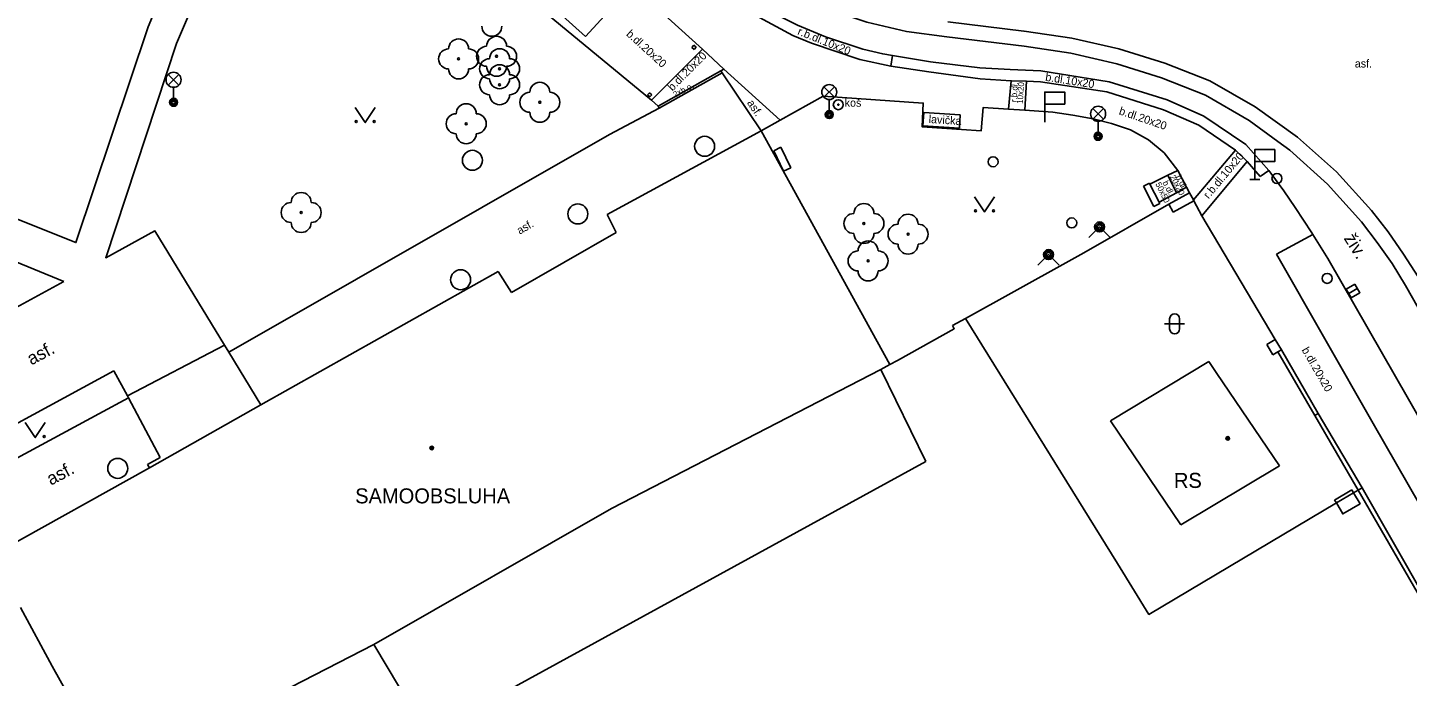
# Model space of a CAD drawing. Extents: x -600391 to -599491, y -1160176 to -1159402.
# Drawn here: x -600032.7 to -599963.7, y -1159815.5 to -1159783.1 of the extents above; entities that cross this region are included whole.
import ezdxf

# ---------------------------------------------------------------- set-up
doc = ezdxf.new("R2010")
doc.units = 0
for name, color, linetype in [('Level 10', 7, 'Continuous'), ('Level 11', 7, 'Continuous'), ('Level 13', 7, 'Continuous'), ('Level 22', 7, 'Continuous'), ('Level 24', 7, 'Continuous'), ('Level 25', 7, 'Continuous'), ('Level 27', 7, 'Continuous'), ('Level 28', 7, 'Continuous'), ('Level 31', 7, 'Continuous'), ('Level 33', 7, 'Continuous'), ('Level 34', 7, 'Continuous'), ('Level 36', 7, 'Continuous'), ('Level 39', 7, 'Continuous'), ('Level 40', 7, 'Continuous'), ('Level 41', 7, 'Continuous'), ('Level 42', 7, 'Continuous'), ('Level 5', 7, 'Continuous'), ('Level 53', 7, 'Continuous'), ('Level 6', 7, 'Continuous'), ('Level 7', 7, 'Continuous'), ('Level 8', 7, 'Continuous')]:
    doc.layers.add(name, color=color, linetype=linetype)

msp = doc.modelspace()

# ---------------------------------------------------------------- linework, layer by layer
at = {"layer": 'Level 10'}
for points in [[(-599996.32, -1159781.8), (-599995.99, -1159782), (-599995.5, -1159782.3), (-599994.17, -1159782.98), (-599992.77, -1159783.55), (-599990.91, -1159784.17)], [(-599985.05, -1159785.11), (-599987.52, -1159784.81), (-599989.42, -1159784.49), (-599989.91, -1159784.41), (-599990.91, -1159784.17)], [(-599985.05, -1159785.11), (-599983.54, -1159785.19)], [(-599983.54, -1159785.19), (-599982.01, -1159785.26), (-599978.59, -1159785.81), (-599975.69, -1159786.71), (-599973.85, -1159787.52), (-599971.76, -1159788.94), (-599970.6, -1159790.24)], [(-599970.6, -1159790.24), (-599970.51, -1159790.37), (-599969.86, -1159791.25)], [(-599969.86, -1159791.25), (-599969.29, -1159792.09), (-599968.46, -1159793.36), (-599968.41, -1159793.44), (-599967.66, -1159794.63)], [(-599969.86, -1159791.25), (-599969.29, -1159792.09), (-599968.46, -1159793.36), (-599968.41, -1159793.44), (-599967.66, -1159794.63)], [(-599967.66, -1159794.63), (-599963.63, -1159801.67), (-599957.71, -1159812.03)]]:
    msp.add_lwpolyline(points, dxfattribs=at)
at = {"layer": 'Level 11'}
for points in [[(-599983.62, -1159787.18), (-599983.48, -1159785.75), (-599985.04, -1159785.65), (-599987.61, -1159785.3), (-599989.51, -1159785.02), (-599991.06, -1159784.69), (-599993.47, -1159783.87), (-599994.4, -1159783.49), (-599996.28, -1159782.47), (-599998.5, -1159780.99), (-600001, -1159778.93), (-600003.59, -1159775.97), (-600005.32, -1159773.3), (-600006.97, -1159769.34), (-600007.51, -1159766.96), (-600007.91, -1159763.43), (-600007.81, -1159760.39)], [(-600001.14, -1159787.02), (-599998, -1159785.25), (-599997.85, -1159785.17), (-599998.92, -1159784.17), (-600002.35, -1159781.06), (-600004.81, -1159778.83), (-600008.12, -1159775.8), (-600008.17, -1159775.75)], [(-600043.13, -1159779.41), (-600038.01, -1159778.77), (-600031.48, -1159778.39), (-600027.46, -1159778.27), (-600025.46, -1159778.33), (-600025.01, -1159779.18), (-600026.63, -1159783.05), (-600030.24, -1159793.84), (-600038.89, -1159790.39)], [(-600022.81, -1159798.97), (-600026.29, -1159793.26), (-600028.75, -1159794.6), (-600025.22, -1159783.89), (-600023.54, -1159779.99), (-600022.13, -1159778.48), (-600016.23, -1159778.91)], [(-600007.53, -1159781.7), (-600001.46, -1159786.72), (-600001.14, -1159787.02), (-600001.09, -1159787.12)], [(-599994.52, -1159781.35), (-599992.65, -1159782.18), (-599990.71, -1159782.82), (-599988.72, -1159783.29), (-599986.7, -1159783.56)], [(-599986.7, -1159783.56), (-599982.83, -1159784.03)], [(-600001.46, -1159786.72), (-599998.92, -1159784.17)], [(-599999.45, -1159784.09), (-599999.35, -1159783.98)], [(-599999.34, -1159784.19), (-599999.45, -1159784.09)], [(-599999.35, -1159783.98), (-599999.24, -1159784.08)], [(-599999.24, -1159784.08), (-599999.34, -1159784.19)], [(-599989.51, -1159785.02), (-599989.42, -1159784.49)], [(-599982.83, -1159784.03), (-599980.5, -1159784.38), (-599978.21, -1159784.91), (-599975.97, -1159785.6), (-599973.78, -1159786.47)], [(-599997.85, -1159785.17), (-599995.04, -1159787.72)], [(-599997.94, -1159785.35), (-600001.09, -1159787.12)], [(-599997.94, -1159785.35), (-599998, -1159785.25)], [(-599997.94, -1159785.35), (-599995.99, -1159788.26)], [(-599983.48, -1159785.75), (-599982.72, -1159785.78)], [(-599982.81, -1159787.22), (-599982.72, -1159785.78), (-599982.03, -1159785.8)], [(-599982.03, -1159785.8), (-599978.7, -1159786.31)], [(-600001.66, -1159786.46), (-600001.56, -1159786.35)], [(-600001.55, -1159786.56), (-600001.66, -1159786.46)], [(-600001.56, -1159786.35), (-600001.45, -1159786.45)], [(-600001.45, -1159786.45), (-600001.55, -1159786.56)], [(-599995.99, -1159788.26), (-599995.04, -1159787.72), (-599992.88, -1159786.53), (-599987.88, -1159786.87), (-599987.94, -1159788.05), (-599984.98, -1159788.25), (-599984.89, -1159787.09), (-599983.62, -1159787.18), (-599982.81, -1159787.22), (-599981.41, -1159787.33), (-599980.41, -1159787.47), (-599979.39, -1159787.65), (-599978.47, -1159787.89), (-599977.53, -1159788.21), (-599976.63, -1159788.71), (-599975.84, -1159789.36), (-599975.16, -1159790.24)], [(-599978.7, -1159786.31), (-599975.87, -1159787.2)], [(-599973.78, -1159786.47), (-599971.59, -1159787.74), (-599970.15, -1159788.79)], [(-600001.09, -1159787.12), (-600003.57, -1159788.44)], [(-599975.87, -1159787.2), (-599974.11, -1159787.98), (-599972.27, -1159789.23)], [(-600003.57, -1159788.44), (-600022.59, -1159799.32)], [(-599972.27, -1159789.23), (-599974.38, -1159791.71)], [(-599972.27, -1159789.23), (-599971.69, -1159789.79)], [(-599970.15, -1159788.79), (-599969.55, -1159789.23), (-599967.67, -1159790.93), (-599965.98, -1159792.81)], [(-599970.15, -1159788.79), (-599969.55, -1159789.23), (-599967.67, -1159790.93), (-599965.98, -1159792.81)], [(-599973.96, -1159792.5), (-599971.69, -1159789.79)], [(-599971.69, -1159789.79), (-599971.04, -1159790.54)], [(-600044.16, -1159790.33), (-600030.85, -1159795.78)], [(-599976.55, -1159790.93), (-599975.65, -1159790.48), (-599975.16, -1159790.24)], [(-599975.65, -1159790.48), (-599975.23, -1159791.35)], [(-599975.16, -1159790.24), (-599974.72, -1159791.07)], [(-599971.04, -1159790.54), (-599970.6, -1159790.24)], [(-599976.09, -1159791.82), (-599975.23, -1159791.35)], [(-599975.23, -1159791.35), (-599974.72, -1159791.07)], [(-599974.72, -1159791.07), (-599974.57, -1159791.36)], [(-599968.41, -1159793.44), (-599970.23, -1159794.42)], [(-599965.98, -1159792.81), (-599965.19, -1159793.83), (-599964.45, -1159794.88), (-599963.77, -1159795.98), (-599963.14, -1159797.1)], [(-599970.23, -1159794.42), (-599965.39, -1159802.89)], [(-600030.85, -1159795.78), (-600037.83, -1159799.59), (-600038.74, -1159800.06)], [(-600036.4, -1159804.62), (-600028.34, -1159800.26)], [(-600028.34, -1159800.26), (-600027.66, -1159801.51)], [(-599987.75, -1159804.78), (-599990.01, -1159800.18)], [(-600029.09, -1159802.4), (-600027.61, -1159801.6)], [(-600035.67, -1159805.96), (-600029.09, -1159802.4)], [(-600026.56, -1159805.11), (-600020.99, -1159801.96)], [(-599955.87, -1159819.09), (-599956.94, -1159817.39), (-599958, -1159815.68), (-599959.04, -1159813.96), (-599965.39, -1159802.89)], [(-600012.67, -1159818.43), (-599987.75, -1159804.78)], [(-599967.23, -1159806.86), (-599967.32, -1159806.72), (-599966.46, -1159806.21)], [(-599966.37, -1159806.35), (-599966.05, -1159806.9), (-599966.91, -1159807.41), (-599967.23, -1159806.86)], [(-599966.46, -1159806.21), (-599966.37, -1159806.35)], [(-600015.35, -1159813.93), (-600012.83, -1159818.16)]]:
    msp.add_lwpolyline(points, dxfattribs=at)
at = {"layer": 'Level 13'}
for points in [[(-599986.66, -1159782.81), (-599982.85, -1159783.28)], [(-599982.84, -1159783.28), (-599980.46, -1159783.63), (-599978.11, -1159784.16), (-599975.8, -1159784.87), (-599973.55, -1159785.76)], [(-599973.55, -1159785.76), (-599971.29, -1159787.05), (-599969.17, -1159788.57), (-599967.23, -1159790.31), (-599965.48, -1159792.24)], [(-599973.55, -1159785.76), (-599971.29, -1159787.05), (-599969.17, -1159788.57), (-599967.23, -1159790.31), (-599965.48, -1159792.24)], [(-599965.48, -1159792.24), (-599964.65, -1159793.31), (-599963.87, -1159794.42)], [(-599963.87, -1159794.42), (-599963.15, -1159795.56), (-599962.49, -1159796.74)]]:
    msp.add_lwpolyline(points, dxfattribs=at)
at = {"layer": 'Level 22'}
for centre in [(-600009.21, -1159784.53), (-600011.11, -1159784.66), (-600009.06, -1159785.15), (-600009.06, -1159785.95), (-600007.05, -1159786.83), (-600010.73, -1159787.9), (-600018.98, -1159792.34), (-599990.85, -1159792.89), (-599988.64, -1159793.42), (-599990.64, -1159794.76)]:
    msp.add_circle(centre, 0.05, dxfattribs=at)
for centre, start, end in [((-600009.45, -1159783.03), 180, 0), ((-600011.11, -1159784.16), 0, 180), ((-600009.21, -1159784.03), 0, 180), ((-600011.61, -1159784.66), 90, 270), ((-600010.61, -1159784.66), 270, 90), ((-600009.71, -1159784.53), 90, 270), ((-600009.06, -1159784.65), 0, 180), ((-600008.71, -1159784.53), 270, 90), ((-600011.11, -1159785.16), 180, 0), ((-600009.56, -1159785.15), 90, 270), ((-600009.21, -1159785.03), 180, 0), ((-600009.06, -1159785.45), 0, 180), ((-600008.56, -1159785.15), 270, 90), ((-600009.56, -1159785.95), 90, 270), ((-600009.06, -1159785.65), 180, 0), ((-600008.56, -1159785.95), 270, 90), ((-600007.05, -1159786.33), 0, 180), ((-600009.06, -1159786.45), 180, 0), ((-600007.55, -1159786.83), 90, 270), ((-600006.55, -1159786.83), 270, 90), ((-600010.73, -1159787.4), 0, 180), ((-600011.23, -1159787.9), 90, 270), ((-600010.23, -1159787.9), 270, 90), ((-600007.05, -1159787.33), 180, 0), ((-600010.73, -1159788.4), 180, 0), ((-600018.98, -1159791.84), 0, 180), ((-600019.48, -1159792.34), 90, 270), ((-600018.48, -1159792.34), 270, 90), ((-599990.85, -1159792.39), 0, 180), ((-599991.35, -1159792.89), 90, 270), ((-599990.35, -1159792.89), 270, 90), ((-599988.64, -1159792.92), 0, 180), ((-600018.98, -1159792.84), 180, 0), ((-599990.85, -1159793.39), 180, 0), ((-599989.14, -1159793.42), 90, 270), ((-599988.14, -1159793.42), 270, 90), ((-599990.64, -1159794.26), 0, 180), ((-599988.64, -1159793.92), 180, 0), ((-599991.14, -1159794.76), 90, 270), ((-599990.14, -1159794.76), 270, 90), ((-599990.64, -1159795.26), 180, 0)]:
    msp.add_arc(centre, 0.5, start, end, dxfattribs=at)
at = {"layer": 'Level 24'}
for points in [[(-599995.36, -1159789.25), (-599995, -1159789.08)], [(-599994.87, -1159790.27), (-599995.36, -1159789.25)], [(-599995, -1159789.08), (-599994.51, -1159790.1)], [(-599994.51, -1159790.1), (-599994.87, -1159790.27)], [(-599976.57, -1159790.88), (-599976.87, -1159791.03)], [(-599976.87, -1159791.03), (-599976.36, -1159792.04)], [(-599976.06, -1159791.89), (-599976.09, -1159791.82), (-599976.55, -1159790.93), (-599976.57, -1159790.88)], [(-599975.61, -1159791.93), (-599974.57, -1159791.36)], [(-599974.57, -1159791.36), (-599974.38, -1159791.71), (-599974.35, -1159791.76)], [(-599976.36, -1159792.04), (-599976.06, -1159791.89)], [(-599975.39, -1159792.33), (-599975.61, -1159791.93)], [(-599974.35, -1159791.76), (-599975.39, -1159792.33)]]:
    msp.add_lwpolyline(points, dxfattribs=at)
at = {"layer": 'Level 25'}
for radius in [0.25, 0.0303]:
    msp.add_circle((-599992.13, -1159786.95), radius, dxfattribs=at)
at = {"layer": 'Level 27'}
msp.add_line((-599966.185, -1159796.133), (-599966.615, -1159796.387), dxfattribs=at)
msp.add_lwpolyline([(-599966.312, -1159795.918), (-599966.742, -1159796.172), (-599966.488, -1159796.602), (-599966.058, -1159796.348)], close=True, dxfattribs=at)
for centre in [(-599998.81, -1159789.03), (-600010.42, -1159789.73), (-600005.15, -1159792.41), (-600011.01, -1159795.7), (-600028.15, -1159805.13)]:
    msp.add_circle(centre, 0.5, dxfattribs=at)
at = {"layer": 'Level 28'}
msp.add_circle((-599984.39, -1159789.8), 0.25, dxfattribs=at)
at = {"layer": 'Level 31'}
for points in [[(-599979.6, -1159793.59), (-599979.07, -1159793.06), (-599978.54, -1159793.59)], [(-599982.15, -1159794.97), (-599981.62, -1159794.44), (-599981.09, -1159794.97)]]:
    msp.add_lwpolyline(points, dxfattribs=at)
for centre, radius in [((-599970.2, -1159790.64), 0.25), ((-599980.46, -1159792.86), 0.25), ((-599979.07, -1159793.06), 0.25), ((-599979.07, -1159793.06), 0.18), ((-599979.07, -1159793.06), 0.11), ((-599981.62, -1159794.44), 0.25), ((-599981.62, -1159794.44), 0.18), ((-599981.62, -1159794.44), 0.11), ((-599967.69, -1159795.63), 0.25)]:
    msp.add_circle(centre, radius, dxfattribs=at)
at = {"layer": 'Level 33'}
for p, q in [((-600025.625, -1159785.97), (-600025.095, -1159785.44)), ((-600025.625, -1159785.44), (-600025.095, -1159785.97)), ((-600025.36, -1159786.08), (-600025.36, -1159786.83)), ((-599992.845, -1159786.58), (-599992.315, -1159786.05)), ((-599992.845, -1159786.05), (-599992.315, -1159786.58)), ((-599992.58, -1159786.69), (-599992.58, -1159787.44)), ((-599979.405, -1159787.67), (-599978.875, -1159787.14)), ((-599979.405, -1159787.14), (-599978.875, -1159787.67)), ((-599979.14, -1159787.78), (-599979.14, -1159788.53))]:
    msp.add_line(p, q, dxfattribs=at)
for centre, radius in [((-600025.36, -1159785.705), 0.375), ((-599992.58, -1159786.315), 0.375), ((-600025.36, -1159786.83), 0.2), ((-600025.36, -1159786.83), 0.145), ((-600025.36, -1159786.83), 0.0876), ((-599992.58, -1159787.44), 0.2), ((-599979.14, -1159787.405), 0.375), ((-599992.58, -1159787.44), 0.145), ((-599992.58, -1159787.44), 0.0876), ((-599979.14, -1159788.53), 0.2), ((-599979.14, -1159788.53), 0.145), ((-599979.14, -1159788.53), 0.0876)]:
    msp.add_circle(centre, radius, dxfattribs=at)
at = {"layer": 'Level 34'}
for p, q in [((-599981.81, -1159786.92), (-599981.81, -1159787.82)), ((-599971.31, -1159789.79), (-599971.31, -1159790.69)), ((-599971.56, -1159790.69), (-599971.06, -1159790.69))]:
    msp.add_line(p, q, dxfattribs=at)
for points in [[(-599981.81, -1159786.92), (-599980.81, -1159786.92), (-599980.81, -1159786.32), (-599981.81, -1159786.32)], [(-599971.31, -1159789.79), (-599970.31, -1159789.79), (-599970.31, -1159789.19), (-599971.31, -1159789.19)]]:
    msp.add_lwpolyline(points, close=True, dxfattribs=at)
at = {"layer": 'Level 36'}
for p, q in [((-599975.816, -1159797.906), (-599974.816, -1159797.906)), ((-599975.566, -1159797.656), (-599975.566, -1159798.156)), ((-599975.066, -1159797.656), (-599975.066, -1159798.156))]:
    msp.add_line(p, q, dxfattribs=at)
for points in [[(-600016.28, -1159787.09), (-600015.78, -1159787.84), (-600015.28, -1159787.09)], [(-599985.32, -1159791.56), (-599984.82, -1159792.31), (-599984.32, -1159791.56)], [(-600032.77, -1159802.84), (-600032.27, -1159803.59), (-600031.77, -1159802.84)]]:
    msp.add_lwpolyline(points, dxfattribs=at)
for centre in [(-600016.23, -1159787.79), (-600015.331, -1159787.79), (-599985.27, -1159792.26), (-599984.371, -1159792.26), (-600031.821, -1159803.54)]:
    msp.add_circle(centre, 0.05, dxfattribs=at)
for centre, start, end in [((-599975.316, -1159797.656), 0, 180), ((-599975.316, -1159798.156), 180, 0)]:
    msp.add_arc(centre, 0.25, start, end, dxfattribs=at)
at = {"layer": 'Level 39'}
for centre, radius in [((-599972.66, -1159803.63), 0.09), ((-599972.66, -1159803.63), 0.0398), ((-600012.45, -1159804.11), 0.09), ((-600012.45, -1159804.11), 0.0398)]:
    msp.add_circle(centre, radius, dxfattribs=at)
at = {"layer": 'Level 5'}
for points in [[(-600004.76, -1159783.54), (-600002.49, -1159781.04)], [(-600007.05, -1159781.48), (-600004.76, -1159783.54)], [(-600003.69, -1159792.44), (-599995.99, -1159788.26)], [(-599995.99, -1159788.26), (-599989.55, -1159799.94)], [(-600003.23, -1159793.33), (-600003.69, -1159792.44)], [(-600008.47, -1159796.34), (-600003.23, -1159793.33)], [(-600020.99, -1159801.96), (-600009.14, -1159795.29)], [(-600009.14, -1159795.29), (-600008.47, -1159796.34)], [(-600022.81, -1159798.97), (-600027.66, -1159801.51)], [(-600022.59, -1159799.32), (-600022.81, -1159798.97)], [(-600020.99, -1159801.96), (-600022.59, -1159799.32)], [(-599989.55, -1159799.94), (-599990.01, -1159800.18), (-600003.47, -1159807.14)], [(-599978.52, -1159802.75), (-599973.61, -1159799.78)], [(-599973.61, -1159799.78), (-599973.2, -1159800.38)], [(-599973.2, -1159800.38), (-599970.07, -1159805)], [(-600027.66, -1159801.51), (-600027.61, -1159801.6), (-600026.03, -1159804.58)], [(-599975, -1159807.96), (-599978.52, -1159802.75)], [(-600033.7, -1159810.82), (-600034.43, -1159809.48), (-600033.98, -1159809.23), (-600026.56, -1159805.11)], [(-600026.03, -1159804.58), (-600026.66, -1159804.94)], [(-600026.66, -1159804.94), (-600026.56, -1159805.11)], [(-599970.07, -1159805), (-599975, -1159807.96)], [(-600003.47, -1159807.14), (-600015.35, -1159813.93)], [(-600033.01, -1159812.09), (-600031.42, -1159815.02)], [(-600015.35, -1159813.93), (-600028.35, -1159820.61)], [(-600031.42, -1159815.02), (-600030.71, -1159816.31)]]:
    msp.add_lwpolyline(points, dxfattribs=at)
at = {"layer": 'Level 53'}
for points in [[(-599987.86, -1159787.34), (-599987.9, -1159788)], [(-599986.03, -1159787.46), (-599987.86, -1159787.34)], [(-599986.07, -1159788.12), (-599986.03, -1159787.46)], [(-599987.9, -1159788), (-599986.07, -1159788.12)]]:
    msp.add_lwpolyline(points, dxfattribs=at)
at = {"layer": 'Level 6'}
msp.add_lwpolyline([(-600031.42, -1159815.02), (-600030.71, -1159816.31)], dxfattribs=at)
at = {"layer": 'Level 7'}
for points in [[(-599979.85, -1159794.35), (-599975.61, -1159791.93)], [(-599974.35, -1159791.76), (-599973.96, -1159792.5), (-599970.29, -1159798.69), (-599969.98, -1159799.2)], [(-599980.76, -1159794.85), (-599985.77, -1159797.63), (-599986.42, -1159797.99)], [(-599986.42, -1159797.99), (-599986.33, -1159798.15), (-599989.17, -1159799.73), (-599989.55, -1159799.94)], [(-599985.77, -1159797.63), (-599978.18, -1159809.88)], [(-599970.29, -1159798.69), (-599970.71, -1159798.94)], [(-599970.4, -1159799.45), (-599970.71, -1159798.94)], [(-599970.15, -1159799.3), (-599970.4, -1159799.45)], [(-599969.98, -1159799.2), (-599970.15, -1159799.3)], [(-599968.31, -1159802.48), (-599970.15, -1159799.3)], [(-599968.14, -1159802.38), (-599969.98, -1159799.2)], [(-599968.14, -1159802.38), (-599968.31, -1159802.48)], [(-599953.24, -1159826.96), (-599955.54, -1159823.5), (-599956.79, -1159821.48), (-599962.84, -1159811.54), (-599965.94, -1159806.1), (-599968.14, -1159802.38)], [(-599963.01, -1159811.64), (-599966.15, -1159806.22), (-599968.31, -1159802.48)], [(-599967.23, -1159806.86), (-599966.37, -1159806.35)], [(-599966.37, -1159806.35), (-599966.15, -1159806.22)], [(-599966.15, -1159806.22), (-599965.94, -1159806.1)], [(-599978.18, -1159809.88), (-599976.6, -1159812.43), (-599967.23, -1159806.86)]]:
    msp.add_lwpolyline(points, dxfattribs=at)
at = {"layer": 'Level 8'}
msp.add_lwpolyline([(-599980.76, -1159794.85), (-599979.85, -1159794.35)], dxfattribs=at)

# ---------------------------------------------------------------- texts
at = {"layer": 'Level 40'}
for s, height, rotation, p in [('b.dl.20x20', 0.4, 317.52877, (-600002.76, -1159783.46)), ('r.b.dl.10x20', 0.4, 338, (-599994.2, -1159783.43)), ('b.dl.20x20', 0.4, 45, (-600000.42, -1159786.29)), ('r.b.dl.', 0.3, 86, (-599983.22, -1159786.83)), ('10x20', 0.3, 86, (-599982.91, -1159786.92)), ('b.dl.10x20', 0.4, 351.23569, (-599981.8, -1159785.75)), ('2xb.o.', 0.3, 28.0245, (-600000.29, -1159786.6)), ('asf.', 0.4, 304, (-599996.71, -1159786.86)), ('b.dl.20x20', 0.4, 341.20011, (-599978.13, -1159787.42)), ('r.b.dl.10x20', 0.4, 50.04917, (-599973.62, -1159791.68)), ('b.dl.', 0.3, 296, (-599975.93, -1159790.84)), ('20x20', 0.3, 298, (-599975.57, -1159790.55)), ('b.dl.', 0.3, 298, (-599975.27, -1159790.56)), ('50x50', 0.3, 296, (-599976.29, -1159790.91)), ('asf.', 0.4, 30, (-600008.06, -1159793.45)), ('živ.', 0.65, 302.3227, (-599966.88, -1159793.63)), ('asf.', 0.65, 28, (-600032.47, -1159799.99)), ('b.dl.20x20', 0.4, 300, (-599968.98, -1159799.21)), ('asf.', 0.65, 28, (-600031.49, -1159806))]:
    msp.add_text(s, height=height, rotation=rotation, dxfattribs=at).set_placement(p)
msp.add_text('asf.', height=0.4, dxfattribs=at).set_placement((-599966.31, -1159785.09))
at = {"layer": 'Level 41'}
msp.add_text('RS', height=0.75, rotation=0.46, dxfattribs=at).set_placement((-599975.35, -1159806.11))
for s, p in [('RS', (-599975.35, -1159806.11)), ('SAMOOBSLUHA', (-600016.28, -1159806.88)), ('SAMOOBSLUHA', (-600016.28, -1159806.88))]:
    msp.add_text(s, height=0.75, dxfattribs=at).set_placement(p)
at = {"layer": 'Level 42'}
msp.add_text('koš', height=0.4, dxfattribs=at).set_placement((-599991.81, -1159787.05))
msp.add_text('lavička', height=0.4, rotation=356.24827, dxfattribs=at).set_placement((-599987.62, -1159787.86))

doc.saveas('drawing.dxf')
